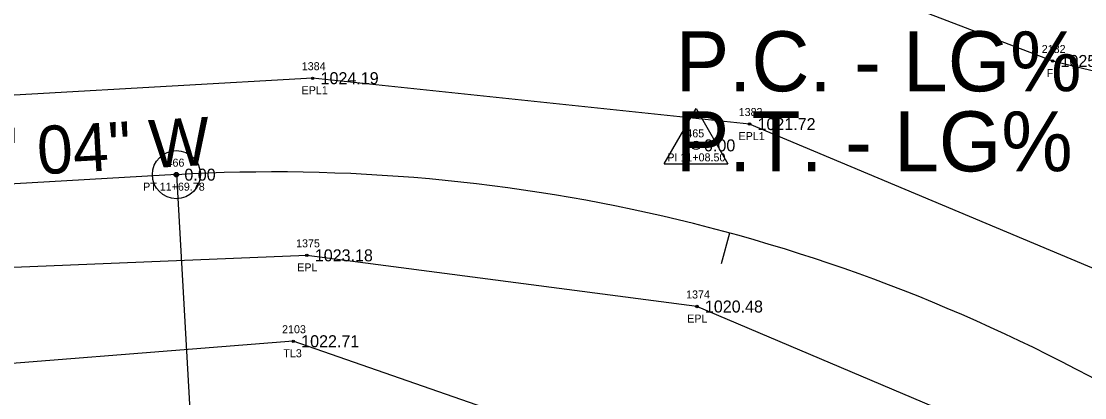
# Model space of a CAD drawing. Extents: x 1578957 to 1581675, y 1115963 to 1120391.
# Drawn here: x 1579963.3 to 1580096.1, y 1117688.7 to 1117735.8 of the extents above; entities that cross this region are included whole.
import ezdxf

# ---------------------------------------------------------------- set-up
doc = ezdxf.new("R2010")
doc.units = 0
for name, color, linetype in [('RD_EX_Fence_Other', 7, 'Continuous'), ('RD_EX_Fence_Other_txCode', 7, 'Continuous'), ('RD_EX_Road', 7, 'Continuous'), ('RD_EX_Road_txCode', 7, 'Continuous'), ('RD_EX_TX_Fence_Other_ELEV', 7, 'Continuous'), ('RD_EX_TX_Road_ELEV', 7, 'Continuous'), ('RD_EX_TX_VEG_ELEV', 7, 'Continuous'), ('RD_EX_VEG', 7, 'Continuous'), ('RD_EX_VEG_txCode', 7, 'Continuous'), ('RD_HC_Cl', 7, 'Continuous'), ('RD_HC_Data', 7, 'Continuous'), ('RD_HC_Data_Tic', 7, 'Continuous'), ('RD_HC_Survey_ELEV', 7, 'Continuous'), ('RD_HC_txCode', 7, 'Continuous'), ('RD_SMD_Locator', 7, 'Continuous')]:
    doc.layers.add(name, color=color, linetype=linetype)

msp = doc.modelspace()

# ---------------------------------------------------------------- linework, layer by layer
at = {"layer": 'RD_EX_Fence_Other'}
msp.add_lwpolyline([(1579823.1, 1118041.09), (1579819.64, 1117977.76), (1579811.21, 1117936.27), (1579806.91, 1117888.2), (1579805.65, 1117872.98), (1579810.22, 1117834.8), (1579821.35, 1117805.11), (1579835.23, 1117784.19), (1579851.4, 1117768.05), (1579868.55, 1117757.56), (1579908.33, 1117744.23), (1579949.73, 1117742.64), (1579998.85, 1117745.11), (1580033.64, 1117749.16), (1580057.08, 1117744.23), (1580092.08, 1117730.79), (1580117.52, 1117724.62), (1580141.72, 1117727.93), (1580159.98, 1117735.31), (1580192.44, 1117760.45), (1580226.97, 1117787.77), (1580271.31, 1117822.49), (1580302.1, 1117858.03)], dxfattribs=at)
at = {"layer": 'RD_EX_Road'}
for points in [[(1580132.91, 1117689.95), (1580126.2, 1117690.71), (1580104.51, 1117701.77), (1580054.23, 1117722.91), (1579999.66, 1117728.64), (1579947.03, 1117725.64), (1579902.62, 1117727.9), (1579859.28, 1117741.23), (1579828.34, 1117764.87), (1579804.42, 1117802.73), (1579793.2, 1117845.91), (1579792.76, 1117891.98), (1579799.63, 1117938.22), (1579807.41, 1117987.51), (1579809.68, 1118039.77), (1579804.46, 1118093.36), (1579794.79, 1118143.94)], [(1580122, 1117647.6), (1580119.9, 1117658.17), (1580108.55, 1117670.89), (1580093.89, 1117680.5), (1580047.66, 1117700.12), (1579998.94, 1117706.51), (1579949.02, 1117704.45), (1579899.18, 1117706.75), (1579851.31, 1117721.6), (1579810.79, 1117752.92), (1579804.03, 1117759.71), (1579792.3, 1117778.19), (1579787.44, 1117787.95), (1579779.12, 1117811.18), (1579772.6, 1117842.3), (1579771.81, 1117848.59), (1579770.15, 1117878.24), (1579771.73, 1117892.02), (1579778.92, 1117940.84), (1579785.85, 1117982.89), (1579786.73, 1117990.34), (1579789.16, 1118040.25), (1579783.45, 1118089.74), (1579774.29, 1118139.39)]]:
    msp.add_lwpolyline(points, dxfattribs=at)
at = {"layer": 'RD_EX_VEG'}
msp.add_lwpolyline([(1579862.33, 1117508.14), (1579987.98, 1117577.14), (1580030.01, 1117601.02), (1580092.8, 1117606.94), (1580099.44, 1117660.22), (1579997.24, 1117695.78), (1579947.95, 1117691.88), (1579838.07, 1117719.77), (1579796.8, 1117753), (1579780.49, 1117738.53), (1579705.63, 1117750.62)], dxfattribs=at)
at = {"layer": 'RD_HC_Cl'}
msp.add_line((1579982.65, 1117716.59), (1579937.3, 1117714.03), dxfattribs=at)
msp.add_arc((1579994.83, 1117500.9), 216.03, 59.7409, 93.2323, dxfattribs=at)
at = {"layer": 'RD_HC_Data'}
for p, q in [((1580043.58, 1117717.96), (1580047.55, 1117724.84)), ((1580047.55, 1117724.84), (1580051.52, 1117717.96)), ((1580043.58, 1117717.96), (1580051.52, 1117717.96)), ((1579982.65, 1117716.59), (1579989.18, 1117601.06))]:
    msp.add_line(p, q, dxfattribs=at)
for centre, radius in [((1580047.55, 1117720.25), 0.529), ((1579982.65, 1117716.59), 3), ((1579982.65, 1117716.59), 0.282)]:
    msp.add_circle(centre, radius, dxfattribs=at)
at = {"layer": 'RD_HC_Data_Tic'}
msp.add_line((1580051.75, 1117709.3), (1580050.69, 1117705.44), dxfattribs=at)
at = {"layer": 'RD_SMD_Locator'}
for centre in [(1580092.08, 1117730.79), (1579999.66, 1117728.64), (1580054.23, 1117722.91), (1580047.55, 1117720.25), (1579982.65, 1117716.59), (1579998.94, 1117706.51), (1580047.66, 1117700.12), (1579997.24, 1117695.78)]:
    msp.add_circle(centre, 0.15, dxfattribs=at)

# ---------------------------------------------------------------- texts
at = {"layer": 'RD_EX_Fence_Other_txCode'}
for s, p in [('2182', (1580090.73, 1117731.79)), ('FL', (1580091.35, 1117728.79))]:
    msp.add_text(s, height=1, dxfattribs=at).set_placement(p)
at = {"layer": 'RD_EX_Road_txCode'}
for s, p in [('1384', (1579998.31, 1117729.64)), ('EPL1', (1579998.29, 1117726.64)), ('1383', (1580052.88, 1117723.91)), ('EPL1', (1580052.86, 1117720.91)), ('1375', (1579997.6, 1117707.51)), ('EPL', (1579997.74, 1117704.51)), ('1374', (1580046.31, 1117701.12)), ('EPL', (1580046.45, 1117698.12))]:
    msp.add_text(s, height=1, dxfattribs=at).set_placement(p)
at = {"layer": 'RD_EX_TX_Fence_Other_ELEV'}
msp.add_text('1025.58', height=1.5, dxfattribs=at).set_placement((1580093.08, 1117730.04))
at = {"layer": 'RD_EX_TX_Road_ELEV'}
for s, p in [('1024.19', (1580000.66, 1117727.89)), ('1021.72', (1580055.23, 1117722.16)), ('1023.18', (1579999.94, 1117705.76)), ('1020.48', (1580048.66, 1117699.37))]:
    msp.add_text(s, height=1.5, dxfattribs=at).set_placement(p)
at = {"layer": 'RD_EX_TX_VEG_ELEV'}
msp.add_text('1022.71', height=1.5, dxfattribs=at).set_placement((1579998.24, 1117695.03))
at = {"layer": 'RD_EX_VEG_txCode'}
for s, p in [('2103', (1579995.85, 1117696.78)), ('TL3', (1579996.01, 1117693.78))]:
    msp.add_text(s, height=1, dxfattribs=at).set_placement(p)
at = {"layer": 'RD_HC_Data'}
for s, p in [('P.C. - LG% = ', (1580045, 1117727)), ('P.T. - LG% = ', (1580045, 1117717))]:
    msp.add_text(s, height=7.5, dxfattribs=at).set_placement(p)
msp.add_text('S 86%%d 46\' 04" W', height=6, rotation=3.2323, dxfattribs=at).set_placement((1579930.84, 1117714.66))
at = {"layer": 'RD_HC_Survey_ELEV'}
for p in [(1580048.55, 1117719.5), (1579983.65, 1117715.84)]:
    msp.add_text('0.00', height=1.5, dxfattribs=at).set_placement(p)
at = {"layer": 'RD_HC_txCode'}
for s, p in [('465', (1580046.34, 1117721.25)), ('PI 11+08.50', (1580043.97, 1117718.25)), ('466', (1579981.42, 1117717.59)), ('PT 11+69.78', (1579978.49, 1117714.59))]:
    msp.add_text(s, height=1, dxfattribs=at).set_placement(p)

doc.saveas('drawing.dxf')
